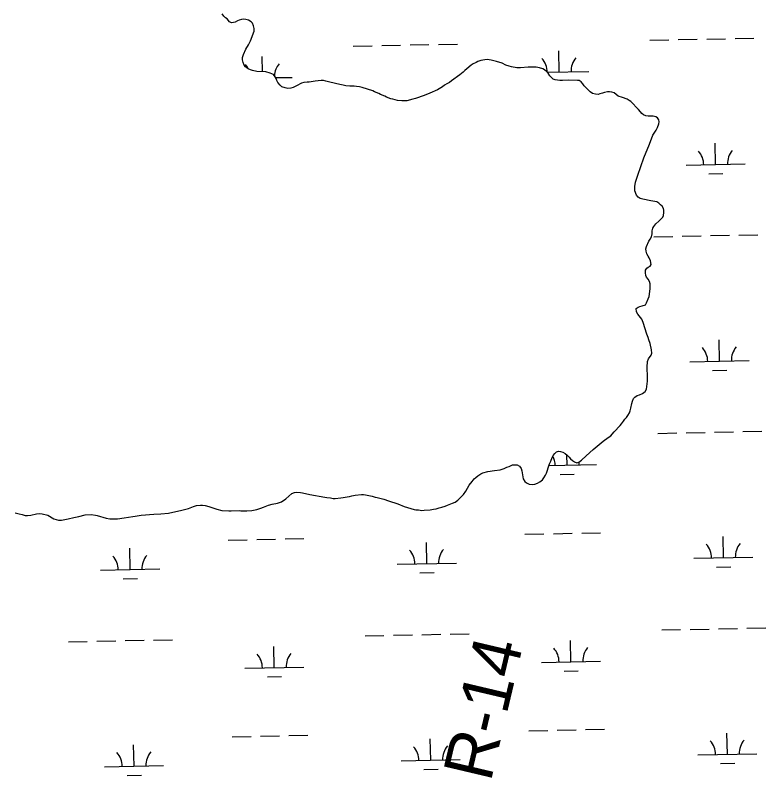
# Model space of a CAD drawing. Extents: x 3989314 to 4027622, y 243956 to 270014.
# Drawn here: x 4015668 to 4016937, y 257601 to 258891 of the extents above; entities that cross this region are included whole.
import ezdxf

# ---------------------------------------------------------------- set-up
doc = ezdxf.new("R2010")
doc.units = 0
for name, color, linetype in [('V-RIVR-EDGE', 7, 'Continuous'), ('V-RIVR-RANG-IDEN', 7, 'Continuous'), ('V-WETL-SWMP', 7, 'Continuous')]:
    doc.layers.add(name, color=color, linetype=linetype)

msp = doc.modelspace()

# ---------------------------------------------------------------- linework, layer by layer
at = {"layer": 'V-RIVR-EDGE'}
for points in [[(4016419.8, 258790.5), (4016405.8, 258780.4), (4016402, 258777.7), (4016397.7, 258775.4), (4016393.9, 258773.1), (4016390.4, 258770.6), (4016381.7, 258765.5), (4016369, 258759.4), (4016359.5, 258755.7), (4016344.7, 258750.7), (4016340.2, 258749.4), (4016330.2, 258746.9), (4016326.6, 258746.4), (4016321.4, 258746.5), (4016314.5, 258747.5), (4016306.4, 258749.3), (4016303.2, 258750.2), (4016295.7, 258753), (4016292.8, 258754.5), (4016285.7, 258757.5), (4016282.9, 258758.9), (4016275.2, 258762.1), (4016272.3, 258763.6), (4016254.3, 258769.2), (4016250.2, 258770.2), (4016245.2, 258770.9), (4016240.8, 258771.2), (4016233.9, 258771.4), (4016227.1, 258772.2), (4016222.3, 258773.3), (4016217, 258774.2), (4016199.8, 258778.3), (4016193.2, 258780.2), (4016189.3, 258780.9), (4016185.3, 258781.1), (4016174.9, 258779.9), (4016164.7, 258778.2), (4016161.3, 258778.5), (4016155.9, 258777.8), (4016152.1, 258776.8), (4016143.6, 258771.8), (4016138, 258769.2), (4016134.1, 258767.9), (4016129, 258767.4), (4016124.4, 258768.5), (4016118.9, 258770.5), (4016115.6, 258773.3), (4016112.1, 258777.8), (4016110.4, 258780.9), (4016108.9, 258784.7), (4016107.6, 258787.5), (4016104.5, 258791), (4016098.8, 258793.7), (4016091.3, 258795.5), (4016076.5, 258796.5), (4016068.8, 258798.1), (4016065.6, 258799), (4016061.7, 258800.7), (4016057.4, 258804), (4016054.9, 258807.2), (4016053.2, 258811.3), (4016052, 258816.1), (4016052.3, 258820.1), (4016053.6, 258824.8), (4016057.8, 258834.3), (4016062, 258841.3), (4016065.4, 258848), (4016071.8, 258864.8), (4016071.9, 258869.3), (4016070.6, 258873.8), (4016068.8, 258878.2), (4016066.6, 258880.4), (4016062.1, 258882.9), (4016057.8, 258884.5), (4016054, 258885), (4016050.2, 258884.5), (4016046.2, 258883.4), (4016043.4, 258882.3), (4016039.9, 258880), (4016036.9, 258879), (4016033.3, 258878.7), (4016030, 258880.2), (4016025.9, 258885.5), (4016023.2, 258887), (4016020.3, 258889.8), (4016017.6, 258893.7)], [(4016747.9, 258534.2), (4016751, 258538.7), (4016756.3, 258543.1), (4016763.1, 258549.7), (4016764.3, 258552.5), (4016764.9, 258557.6), (4016764.8, 258561.4), (4016764.2, 258564.4), (4016762, 258568.3), (4016759.4, 258570.9), (4016756.1, 258573.6), (4016752.8, 258575.7), (4016749.4, 258576.4), (4016742.9, 258577.3), (4016729, 258580.1), (4016724.5, 258581.6), (4016721.3, 258583.7), (4016718.4, 258587.3), (4016715.8, 258594.4), (4016715.5, 258597.8), (4016715.6, 258602), (4016717, 258609.1), (4016717.9, 258612.3), (4016720.7, 258621.1), (4016730.7, 258650.2), (4016740.4, 258673.2), (4016746.4, 258688.8), (4016751.6, 258697.2), (4016754, 258701.7), (4016756.1, 258707.5), (4016756.8, 258711.4), (4016756.5, 258714.4), (4016754.2, 258717.7), (4016751, 258719.4), (4016746.7, 258720.5), (4016742.9, 258720.8), (4016738.5, 258720.7), (4016734.6, 258721.4), (4016730.6, 258722.9), (4016727.7, 258725.2), (4016725.2, 258727.8), (4016721.9, 258731.9), (4016718.8, 258735.4), (4016712.2, 258742.3), (4016708.7, 258745.4), (4016706, 258747.5), (4016702.6, 258749.3), (4016694.9, 258752.5), (4016687.6, 258754.5), (4016683.9, 258757.2), (4016681, 258760.3), (4016677.1, 258761.6), (4016672.9, 258762.1), (4016669.5, 258762), (4016664.5, 258760.9), (4016660.9, 258759.6), (4016656.7, 258758.3), (4016653.6, 258757.6), (4016649.1, 258757.7), (4016644.1, 258759.3), (4016640, 258762), (4016633.4, 258768.5), (4016630.3, 258772), (4016627.8, 258775.6), (4016625.1, 258778.9), (4016621.8, 258780.8), (4016618.6, 258781.3), (4016603.7, 258781.5), (4016593.1, 258780.9), (4016588.9, 258781.1), (4016581.2, 258782.1), (4016577.6, 258783.5), (4016575.1, 258785.4), (4016572.2, 258788.7), (4016568.9, 258793.3), (4016566.2, 258796.2), (4016562.9, 258799.3), (4016560, 258800.7), (4016554.4, 258802.3), (4016548.7, 258803.4), (4016544.9, 258803.5), (4016535.5, 258803.4), (4016522.6, 258802.5), (4016516, 258802.7), (4016507.3, 258804.3), (4016503.3, 258805.6), (4016497.8, 258807.2), (4016491.1, 258810.2), (4016482, 258813.4), (4016472.9, 258815.6), (4016466.1, 258816.4), (4016461.8, 258816.3), (4016455.1, 258814.7), (4016450.3, 258813.2), (4016447.1, 258811.7), (4016442.2, 258809.1), (4016439, 258806.8), (4016431.5, 258800.6), (4016428.2, 258797.9), (4016425.1, 258795), (4016419.8, 258790.5)], [(4016568.2, 258122), (4016569.3, 258125.9), (4016571.4, 258132.3), (4016573.8, 258137.2), (4016576.1, 258143.1), (4016577.8, 258146.6), (4016580.3, 258150.1), (4016583.3, 258152.7), (4016586.7, 258153.8), (4016589.9, 258153.5), (4016593.9, 258152), (4016597.8, 258150.1), (4016601.3, 258147), (4016604.8, 258143.5), (4016606.9, 258141.1), (4016610.2, 258138), (4016613.4, 258135.9), (4016617.9, 258134), (4016620.9, 258135.3), (4016625.6, 258138.6), (4016633.4, 258146.1), (4016645, 258156.8), (4016662.1, 258170.7), (4016670.6, 258177.2), (4016674.9, 258180.1), (4016677.6, 258182.4), (4016680.9, 258186.5), (4016690.9, 258197.4), (4016693, 258200.3), (4016696.5, 258204.8), (4016699, 258207.9), (4016701.4, 258210.7), (4016704.1, 258214.2), (4016706.6, 258218.7), (4016707.7, 258222.1), (4016708.8, 258226.4), (4016710.6, 258234.7), (4016711.7, 258238.3), (4016713.6, 258242.8), (4016715.7, 258245.4), (4016719.6, 258248), (4016723.4, 258249.3), (4016728.6, 258251.6), (4016733.3, 258254.6), (4016735.6, 258259), (4016737.3, 258272.1), (4016737.2, 258275.3), (4016737.3, 258278.6), (4016737, 258284), (4016736.4, 258291.2), (4016736.4, 258296), (4016737.2, 258305.5), (4016739.1, 258310.1), (4016743.5, 258316.5), (4016744.4, 258319.9), (4016743.9, 258325.5), (4016741.6, 258335.9), (4016739.2, 258342.5), (4016738.3, 258346), (4016736.1, 258351.6), (4016730, 258371.7), (4016727.4, 258377.1), (4016725.5, 258379.8), (4016720.6, 258385.7), (4016718.5, 258389.7), (4016718.1, 258395.3), (4016721.1, 258397.6), (4016724.2, 258398.7), (4016728.4, 258399.6), (4016733.6, 258401.5), (4016735.7, 258405), (4016738.5, 258411.7), (4016739.8, 258415.6), (4016740.7, 258419.8), (4016741.7, 258429.3), (4016741.8, 258432.9), (4016741.5, 258437.1), (4016740.4, 258440.9), (4016738.1, 258444.8), (4016735.6, 258448.4), (4016734.5, 258451.4), (4016733.5, 258455.7), (4016733.8, 258460.4), (4016736, 258463.4), (4016738.5, 258465.3), (4016741.9, 258466.8), (4016743.4, 258469.5), (4016742.2, 258476.1), (4016740.1, 258481.2), (4016738.2, 258484), (4016736.3, 258487.7), (4016734.8, 258492.5), (4016734.3, 258496.3), (4016735.6, 258500.4), (4016739.5, 258509.3), (4016741.7, 258512.8), (4016743.8, 258516.7), (4016744.8, 258521.5), (4016745.3, 258526.7), (4016746.4, 258531), (4016747.9, 258534.2)], [(4015974.5, 258061.7), (4015981.1, 258062.7), (4015984.7, 258062.6), (4015989, 258061.7), (4015995, 258060.2), (4016008.4, 258055.6), (4016017.3, 258053.6), (4016029.2, 258052.9), (4016032.8, 258053.2), (4016046.2, 258053.4), (4016049.4, 258053.1), (4016059.5, 258052.9), (4016068.1, 258053.4), (4016076.1, 258055.2), (4016079.5, 258056.3), (4016083.1, 258057.2), (4016087.8, 258059.3), (4016096, 258062.6), (4016102.1, 258064.5), (4016111.1, 258066.2), (4016117.9, 258068.4), (4016125.2, 258073), (4016135.6, 258082.3), (4016140, 258083.8), (4016144.2, 258084.3), (4016150, 258083.7), (4016153.4, 258083.2), (4016165.8, 258080.5), (4016191.6, 258076.2), (4016194.8, 258075.6), (4016200.7, 258074.8), (4016205.5, 258073.9), (4016208.9, 258073.8), (4016218.3, 258074.7), (4016222.5, 258075.6), (4016228.9, 258076.4), (4016233.1, 258077.3), (4016237.1, 258078.4), (4016242.5, 258079.5), (4016253.1, 258080.6), (4016256.5, 258080.5), (4016260.2, 258080), (4016271.5, 258077.5), (4016276.3, 258076.2), (4016279.9, 258075.5), (4016291.1, 258072.6), (4016299.2, 258070), (4016314.6, 258064.6), (4016325.5, 258060.3), (4016342.5, 258055.3), (4016345.4, 258054.8), (4016349.6, 258054.5), (4016355.2, 258053.7), (4016359.2, 258053.8), (4016369.3, 258054.8), (4016375.1, 258055.6), (4016379.4, 258056.5), (4016384.8, 258058.1), (4016389.2, 258059.2), (4016394.8, 258060.9), (4016399, 258062.3), (4016407.5, 258065.7), (4016411.7, 258067.8), (4016416.4, 258071), (4016419.3, 258073.6), (4016422.7, 258077.1), (4016425.8, 258080.8), (4016429.6, 258086.4), (4016435.4, 258096.2), (4016440.4, 258102.7), (4016444.1, 258107.2), (4016446.5, 258109.1), (4016450.2, 258112.4), (4016455.2, 258115.6), (4016458.7, 258117.1), (4016466.9, 258119.3), (4016478.3, 258121.2), (4016487.7, 258122.3), (4016491.5, 258123.2), (4016494.7, 258124.3), (4016499.2, 258126.6), (4016503, 258127.9), (4016509, 258130.7), (4016512, 258131), (4016516.8, 258130.7), (4016520.7, 258128.6), (4016523.2, 258124.8), (4016524.5, 258120.6), (4016527.1, 258107.3), (4016529.4, 258102.7), (4016532.3, 258100.4), (4016537.1, 258098.1), (4016543.2, 258097.3), (4016546.4, 258097.9), (4016551.2, 258099.7), (4016555.1, 258102), (4016559.4, 258105.5), (4016562, 258108.8), (4016564.8, 258113.5), (4016566.4, 258116.8), (4016568.2, 258122)], [(4015667.6, 258049.8), (4015674.5, 258047.6), (4015679.2, 258046.5), (4015684.6, 258045.3), (4015688.5, 258044.8), (4015693.9, 258045.5), (4015703.8, 258048), (4015708, 258048.7), (4015713.3, 258048.1), (4015722.6, 258045.5), (4015733, 258039.6), (4015737, 258038.1), (4015741.1, 258037), (4015745.9, 258037.3), (4015754.1, 258038.7), (4015757.3, 258039.6), (4015766.6, 258041.7), (4015775.4, 258043.5), (4015786.2, 258046), (4015796, 258046.5), (4015803.3, 258045.7), (4015806.5, 258045.1), (4015821.3, 258040.3), (4015827.5, 258039.5), (4015832.4, 258039.2), (4015840.4, 258039.6), (4015851.8, 258041.1), (4015866.8, 258043.5), (4015870.8, 258043.9), (4015880.8, 258045.7), (4015902.2, 258047.3), (4015914.1, 258047.8), (4015926.7, 258049.2), (4015949.6, 258054.2), (4015961, 258057.1), (4015969.1, 258060.1), (4015974.5, 258061.7)]]:
    msp.add_lwpolyline(points, dxfattribs=at)
at = {"layer": 'V-WETL-SWMP'}
for p, q in [((4016335.5, 258841.2), (4016367.5, 258841.8)), ((4016383.5, 258842.1), (4016415.5, 258842.8)), ((4016741.3, 258849.3), (4016773.3, 258849.9)), ((4016789.3, 258850.2), (4016821.3, 258850.8)), ((4016837.3, 258851.2), (4016869.3, 258851.8)), ((4016885.3, 258852.1), (4016917.3, 258852.8)), ((4016239.5, 258839.2), (4016271.5, 258839.9)), ((4016287.5, 258840.2), (4016319.5, 258840.8)), ((4016587.8, 258795.4), (4016587.1, 258831.4)), ((4016085.8, 258795.9), (4016085.2, 258821.4)), ((4016567.3, 258795), (4016637.8, 258796.4)), ((4016108.3, 258785.9), (4016135.9, 258786.4)), ((4016852.4, 258638.8), (4016851.7, 258674.8)), ((4016802.4, 258637.8), (4016902.4, 258639.8)), ((4016840.7, 258623.2), (4016864.7, 258623.6)), ((4016843.9, 258518.6), (4016875.9, 258519.2)), ((4016891.9, 258519.5), (4016923.9, 258520.1)), ((4016747.9, 258516.6), (4016779.9, 258517.3)), ((4016795.9, 258517.6), (4016827.9, 258518.2)), ((4016859, 258306.2), (4016858.3, 258342.2)), ((4016809, 258305.2), (4016909, 258307.2)), ((4016847.3, 258290.5), (4016871.3, 258291)), ((4016754.6, 258184), (4016786.6, 258184.7)), ((4016802.6, 258185), (4016834.6, 258185.6)), ((4016850.6, 258185.9), (4016882.5, 258186.6)), ((4016898.5, 258186.9), (4016930.5, 258187.5)), ((4016601, 258130.2), (4016600.7, 258147.6)), ((4016570.5, 258129.6), (4016651, 258131.2)), ((4016589.3, 258114.6), (4016613.3, 258115)), ((4016625.9, 258015.3), (4016657.9, 258015.9)), ((4016028.1, 258003.3), (4016060.1, 258004)), ((4016076.1, 258004.3), (4016108.1, 258004.9)), ((4016124.1, 258005.3), (4016156.1, 258005.9)), ((4016529.9, 258013.3), (4016561.9, 258014)), ((4016577.9, 258014.3), (4016609.9, 258014.9)), ((4016865.6, 257973.6), (4016864.9, 258009.6)), ((4016363.8, 257963.6), (4016363.1, 257999.6)), ((4015862, 257953.6), (4015861.3, 257989.6)), ((4016313.8, 257962.6), (4016413.8, 257964.6)), ((4016815.6, 257972.6), (4016915.6, 257974.6)), ((4015812, 257952.6), (4015912, 257954.6)), ((4016853.9, 257957.9), (4016877.9, 257958.4)), ((4015850.3, 257937.9), (4015874.3, 257938.4)), ((4016352.1, 257947.9), (4016376.1, 257948.4)), ((4016761.2, 257851.4), (4016793.2, 257852.1)), ((4016809.2, 257852.4), (4016841.2, 257853)), ((4016857.2, 257853.3), (4016889.2, 257854)), ((4016905.2, 257854.3), (4016937.2, 257854.9)), ((4016259.4, 257841.4), (4016291.4, 257842.1)), ((4016307.4, 257842.4), (4016339.4, 257843)), ((4016355.4, 257843.3), (4016387.4, 257844)), ((4016403.4, 257844.3), (4016435.4, 257844.9)), ((4015757.6, 257831.4), (4015789.6, 257832.1)), ((4015805.6, 257832.4), (4015837.6, 257833)), ((4015853.6, 257833.3), (4015885.6, 257834)), ((4015901.6, 257834.3), (4015933.6, 257834.9)), ((4016105.8, 257787.6), (4016105.1, 257823.6)), ((4016607.7, 257797.6), (4016606.9, 257833.6)), ((4016557.7, 257796.6), (4016657.6, 257798.6)), ((4016055.9, 257786.6), (4016155.8, 257788.6)), ((4016094.2, 257771.9), (4016118.2, 257772.4)), ((4016596, 257781.9), (4016620, 257782.4)), ((4016536.6, 257680.7), (4016568.6, 257681.4)), ((4016584.6, 257681.7), (4016616.5, 257682.3)), ((4016632.5, 257682.7), (4016664.5, 257683.3)), ((4016034.8, 257670.7), (4016066.7, 257671.4)), ((4016082.7, 257671.7), (4016114.7, 257672.3)), ((4016130.7, 257672.7), (4016162.7, 257673.3)), ((4016872.3, 257641), (4016871.5, 257677)), ((4015868.6, 257621), (4015867.9, 257657)), ((4016370.5, 257631), (4016369.7, 257667)), ((4016822.3, 257640), (4016922.3, 257642)), ((4016320.5, 257630), (4016420.4, 257632)), ((4015818.7, 257620), (4015918.6, 257622)), ((4016358.8, 257615.3), (4016382.8, 257615.8)), ((4016860.6, 257625.3), (4016884.6, 257625.8)), ((4015857, 257605.3), (4015881, 257605.8))]:
    msp.add_line(p, q, dxfattribs=at)
for points in [[(4016062, 258841.3), (4016065.4, 258848), (4016071.8, 258864.8), (4016071.9, 258869.3), (4016070.6, 258873.8), (4016068.8, 258878.2), (4016066.6, 258880.4), (4016062.1, 258882.9), (4016057.8, 258884.5), (4016054, 258885), (4016050.2, 258884.5), (4016046.2, 258883.4), (4016043.4, 258882.3), (4016039.9, 258880), (4016036.9, 258879), (4016033.3, 258878.7), (4016030, 258880.2), (4016025.9, 258885.5), (4016023.2, 258887), (4016020.3, 258889.8), (4016017.6, 258893.7)], [(4016621.8, 258780.8), (4016618.6, 258781.3), (4016603.7, 258781.5), (4016593.1, 258780.9), (4016588.9, 258781.1), (4016581.2, 258782.1), (4016577.6, 258783.5), (4016575.1, 258785.4), (4016572.2, 258788.7), (4016568.9, 258793.3), (4016566.2, 258796.2), (4016562.9, 258799.3), (4016560, 258800.7), (4016554.4, 258802.3), (4016548.7, 258803.4), (4016544.9, 258803.5), (4016535.5, 258803.4), (4016522.6, 258802.5), (4016516, 258802.7), (4016507.3, 258804.3), (4016503.3, 258805.6), (4016497.8, 258807.2), (4016491.1, 258810.2), (4016482, 258813.4), (4016472.9, 258815.6), (4016466.1, 258816.4), (4016461.8, 258816.3), (4016455.1, 258814.7), (4016450.3, 258813.2), (4016447.1, 258811.7), (4016442.2, 258809.1), (4016439, 258806.8), (4016431.5, 258800.6), (4016428.2, 258797.9), (4016425.1, 258795), (4016419.8, 258790.5), (4016405.8, 258780.4), (4016402, 258777.7), (4016397.7, 258775.4), (4016393.9, 258773.1), (4016390.4, 258770.6), (4016381.7, 258765.5), (4016369, 258759.4), (4016359.5, 258755.7), (4016344.7, 258750.7), (4016340.2, 258749.4), (4016330.2, 258746.9), (4016326.6, 258746.4), (4016321.4, 258746.5), (4016314.5, 258747.5), (4016306.4, 258749.3), (4016303.2, 258750.2), (4016295.7, 258753), (4016292.8, 258754.5), (4016285.7, 258757.5), (4016282.9, 258758.9), (4016275.2, 258762.1), (4016272.3, 258763.6), (4016254.3, 258769.2), (4016250.2, 258770.2), (4016245.2, 258770.9), (4016240.8, 258771.2), (4016233.9, 258771.4), (4016227.1, 258772.2), (4016222.3, 258773.3), (4016217, 258774.2), (4016199.8, 258778.3), (4016193.2, 258780.2), (4016189.3, 258780.9), (4016185.3, 258781), (4016174.9, 258779.9), (4016164.7, 258778.2), (4016161.3, 258778.5), (4016155.9, 258777.8), (4016152.1, 258776.8), (4016143.6, 258771.8), (4016138, 258769.2), (4016134.1, 258767.9), (4016129, 258767.4), (4016124.4, 258768.5), (4016118.9, 258770.5), (4016115.6, 258773.3), (4016112.1, 258777.8), (4016110.4, 258780.9), (4016108.9, 258784.7), (4016107.6, 258787.5), (4016104.5, 258791), (4016098.8, 258793.7), (4016091.3, 258795.5), (4016076.5, 258796.5), (4016068.8, 258798.1), (4016065.6, 258799), (4016061.7, 258800.7), (4016057.4, 258804), (4016054.9, 258807.2), (4016053.2, 258811.3), (4016052, 258816.1), (4016052.3, 258820.1), (4016053.6, 258824.8), (4016057.8, 258834.3), (4016062, 258841.3)], [(4016718.1, 258395.3), (4016721.1, 258397.6), (4016724.2, 258398.7), (4016728.4, 258399.6), (4016733.6, 258401.5), (4016735.7, 258405), (4016738.5, 258411.7), (4016739.8, 258415.6), (4016740.7, 258419.8), (4016741.7, 258429.3), (4016741.8, 258432.9), (4016741.5, 258437.1), (4016740.4, 258440.9), (4016738.1, 258444.8), (4016735.6, 258448.4), (4016734.5, 258451.4), (4016733.5, 258455.7), (4016733.8, 258460.4), (4016736, 258463.4), (4016738.5, 258465.3), (4016741.9, 258466.8), (4016743.4, 258469.5), (4016742.2, 258476.1), (4016740.1, 258481.2), (4016738.2, 258484), (4016736.3, 258487.7), (4016734.8, 258492.5), (4016734.3, 258496.3), (4016735.6, 258500.4), (4016739.5, 258509.3), (4016741.7, 258512.8), (4016743.8, 258516.7), (4016744.8, 258521.5), (4016745.3, 258526.7), (4016746.4, 258531), (4016747.9, 258534.2), (4016751, 258538.7), (4016756.3, 258543.1), (4016763.1, 258549.7), (4016764.3, 258552.5), (4016764.9, 258557.6), (4016764.8, 258561.4), (4016764.2, 258564.4), (4016762, 258568.3), (4016759.4, 258570.9), (4016756.1, 258573.6), (4016752.8, 258575.7), (4016749.4, 258576.4), (4016742.9, 258577.3), (4016729, 258580.1), (4016724.5, 258581.6), (4016721.3, 258583.7), (4016718.4, 258587.3), (4016715.8, 258594.4), (4016715.5, 258597.8), (4016715.6, 258602), (4016717, 258609.1), (4016717.9, 258612.3), (4016720.7, 258621.1), (4016730.7, 258650.2), (4016740.4, 258673.2), (4016746.4, 258688.8), (4016751.6, 258697.2), (4016754, 258701.7), (4016756.1, 258707.5), (4016756.8, 258711.4), (4016756.5, 258714.4), (4016754.2, 258717.7), (4016751, 258719.4), (4016746.7, 258720.5), (4016742.9, 258720.8), (4016738.5, 258720.7), (4016734.6, 258721.4), (4016730.6, 258722.9), (4016727.7, 258725.2), (4016725.2, 258727.8), (4016721.9, 258731.9), (4016718.8, 258735.4), (4016712.2, 258742.3), (4016708.7, 258745.4), (4016706, 258747.5), (4016702.6, 258749.3), (4016694.9, 258752.5), (4016687.6, 258754.5), (4016683.9, 258757.2), (4016681, 258760.3), (4016677.1, 258761.6), (4016672.9, 258762.1), (4016669.5, 258762), (4016664.5, 258760.9), (4016660.9, 258759.6), (4016656.7, 258758.3), (4016653.6, 258757.6), (4016649.1, 258757.7), (4016644.1, 258759.3), (4016640, 258762), (4016633.4, 258768.5), (4016630.3, 258772), (4016627.8, 258775.6), (4016625.1, 258778.9), (4016621.8, 258780.8)], [(4016422.7, 258077), (4016425.8, 258080.8), (4016429.6, 258086.4), (4016435.4, 258096.2), (4016440.4, 258102.7), (4016444.1, 258107.2), (4016446.5, 258109.1), (4016450.2, 258112.4), (4016455.2, 258115.6), (4016458.7, 258117.1), (4016466.9, 258119.3), (4016478.3, 258121.2), (4016487.7, 258122.3), (4016491.5, 258123.2), (4016494.7, 258124.3), (4016499.2, 258126.6), (4016503, 258127.9), (4016509, 258130.7), (4016512, 258131), (4016516.8, 258130.7), (4016520.7, 258128.6), (4016523.2, 258124.8), (4016524.5, 258120.6), (4016527.1, 258107.3), (4016529.4, 258102.7), (4016532.3, 258100.4), (4016537.1, 258098.1), (4016543.2, 258097.3), (4016546.4, 258097.9), (4016551.2, 258099.7), (4016555.1, 258102), (4016559.4, 258105.5), (4016562, 258108.8), (4016564.8, 258113.5), (4016566.4, 258116.8), (4016568.2, 258122), (4016569.3, 258125.9), (4016571.4, 258132.3), (4016573.8, 258137.2), (4016576.1, 258143.1), (4016577.8, 258146.6), (4016580.3, 258150.1), (4016583.3, 258152.7), (4016586.7, 258153.8), (4016589.9, 258153.5), (4016593.9, 258152), (4016597.8, 258150.1), (4016601.3, 258147), (4016604.8, 258143.5), (4016606.9, 258141.1), (4016610.2, 258138), (4016613.4, 258135.9), (4016617.9, 258134), (4016620.9, 258135.3), (4016625.6, 258138.6), (4016633.4, 258146.1), (4016645, 258156.8), (4016662.1, 258170.7), (4016670.6, 258177.2), (4016674.9, 258180.1), (4016677.6, 258182.4), (4016680.9, 258186.5), (4016690.9, 258197.4), (4016693, 258200.3), (4016696.5, 258204.8), (4016699, 258207.9), (4016701.4, 258210.7), (4016704.1, 258214.2), (4016706.6, 258218.7), (4016707.7, 258222.1), (4016708.8, 258226.4), (4016710.6, 258234.7), (4016711.7, 258238.3), (4016713.6, 258242.8), (4016715.7, 258245.4), (4016719.6, 258248), (4016723.4, 258249.3), (4016728.6, 258251.6), (4016733.3, 258254.6), (4016735.6, 258259), (4016737.3, 258272.1), (4016737.2, 258275.3), (4016737.3, 258278.6), (4016737, 258284), (4016736.4, 258291.2), (4016736.4, 258296), (4016737.2, 258305.5), (4016739.1, 258310.1), (4016743.5, 258316.5), (4016744.4, 258319.9), (4016743.9, 258325.5), (4016741.6, 258335.9), (4016739.2, 258342.5), (4016738.3, 258346), (4016736.1, 258351.6), (4016730, 258371.7), (4016727.4, 258377.1), (4016725.5, 258379.8), (4016720.6, 258385.7), (4016718.5, 258389.7), (4016718.1, 258395.3)], [(4015674.5, 258047.6), (4015679.2, 258046.5), (4015684.6, 258045.3), (4015688.5, 258044.8), (4015693.9, 258045.5), (4015703.8, 258048), (4015708, 258048.7), (4015713.3, 258048.1), (4015722.6, 258045.5), (4015733, 258039.6), (4015737, 258038.1), (4015741.1, 258037), (4015745.9, 258037.3), (4015754.1, 258038.7), (4015757.3, 258039.6), (4015766.6, 258041.7), (4015775.4, 258043.5), (4015786.2, 258046), (4015796, 258046.5), (4015803.3, 258045.7), (4015806.5, 258045.1), (4015821.3, 258040.3), (4015827.5, 258039.5), (4015832.4, 258039.2), (4015840.4, 258039.6), (4015851.8, 258041.1), (4015866.8, 258043.5), (4015870.8, 258043.9), (4015880.8, 258045.7), (4015902.2, 258047.3), (4015914.1, 258047.8), (4015926.7, 258049.2), (4015949.6, 258054.2), (4015961, 258057.1), (4015969.1, 258060.1), (4015974.5, 258061.7), (4015981.1, 258062.7), (4015984.7, 258062.6), (4015989, 258061.7), (4015995, 258060.2), (4016008.4, 258055.6), (4016017.3, 258053.6), (4016029.2, 258052.9), (4016032.8, 258053.2), (4016046.2, 258053.4), (4016049.4, 258053.1), (4016059.5, 258052.9), (4016068.1, 258053.4), (4016076.1, 258055.2), (4016079.5, 258056.3), (4016083.1, 258057.2), (4016087.8, 258059.3), (4016096, 258062.6), (4016102.1, 258064.5), (4016111.1, 258066.2), (4016117.9, 258068.4), (4016125.2, 258073), (4016135.6, 258082.3), (4016140, 258083.8), (4016144.2, 258084.3), (4016150, 258083.7), (4016153.4, 258083.2), (4016165.8, 258080.5), (4016191.6, 258076.2), (4016194.8, 258075.6), (4016200.7, 258074.8), (4016205.5, 258073.9), (4016208.9, 258073.8), (4016218.3, 258074.7), (4016222.5, 258075.6), (4016228.9, 258076.4), (4016233.1, 258077.3), (4016237.1, 258078.4), (4016242.5, 258079.5), (4016253.1, 258080.6), (4016256.5, 258080.5), (4016260.2, 258080), (4016271.5, 258077.5), (4016276.3, 258076.2), (4016279.9, 258075.5), (4016291.1, 258072.6), (4016299.2, 258070), (4016314.6, 258064.6), (4016325.5, 258060.3), (4016342.5, 258055.3), (4016345.4, 258054.8), (4016349.6, 258054.5), (4016355.2, 258053.7), (4016359.2, 258053.8), (4016369.3, 258054.8), (4016375.1, 258055.6), (4016379.4, 258056.5), (4016384.8, 258058.1), (4016389.2, 258059.2), (4016394.8, 258060.9), (4016399, 258062.3), (4016407.5, 258065.7), (4016411.7, 258067.8), (4016416.4, 258071), (4016419.3, 258073.6), (4016422.7, 258077)], [(4015667.6, 258049.8), (4015674.5, 258047.6)]]:
    msp.add_lwpolyline(points, dxfattribs=at)
for centre, start, end in [((4016532.5, 258794.8), 0.3699, 41.9135), ((4016643, 258797), 140.3699, 181.9135), ((4016030.7, 258784.8), 26.2786, 41.9135), ((4016141.2, 258787), 140.3699, 176.3378), ((4016797.1, 258638.2), 0.3699, 41.9135), ((4016907.6, 258640.4), 140.3699, 181.9135), ((4016803.8, 258305.6), 0.3699, 41.9135), ((4016914.2, 258307.8), 140.3699, 181.9135), ((4016545.8, 258129.6), 0.3699, 26.7933), ((4016656.2, 258131.8), 173.9483, 181.9135), ((4016810.4, 257973), 0.3699, 41.9135), ((4016920.9, 257975.2), 140.3699, 181.9135), ((4015917.2, 257955.2), 140.3699, 181.9135), ((4016308.6, 257963), 0.3699, 41.9135), ((4016419, 257965.2), 140.3699, 181.9135), ((4015806.8, 257953), 0.3699, 41.9135), ((4016050.6, 257787), 0.3699, 41.9135), ((4016161.1, 257789.2), 140.3699, 181.9135), ((4016552.4, 257797), 0.3699, 41.9135), ((4016662.9, 257799.2), 140.3699, 181.9135), ((4016425.7, 257632.6), 140.3699, 181.9135), ((4016817, 257640.4), 0.3699, 41.9135), ((4016927.5, 257642.6), 140.3699, 181.9135), ((4015813.4, 257620.4), 0.3699, 41.9135), ((4015923.9, 257622.6), 140.3699, 181.9135), ((4016315.2, 257630.4), 0.3699, 41.9135)]:
    msp.add_arc(centre, 35.2, start, end, dxfattribs=at)

# ---------------------------------------------------------------- texts
at = {"layer": 'V-RIVR-RANG-IDEN'}
msp.add_text('R-14 ', height=83, rotation=76.7165, dxfattribs=at).set_placement((4016471.7, 257592.5))

doc.saveas('drawing.dxf')
